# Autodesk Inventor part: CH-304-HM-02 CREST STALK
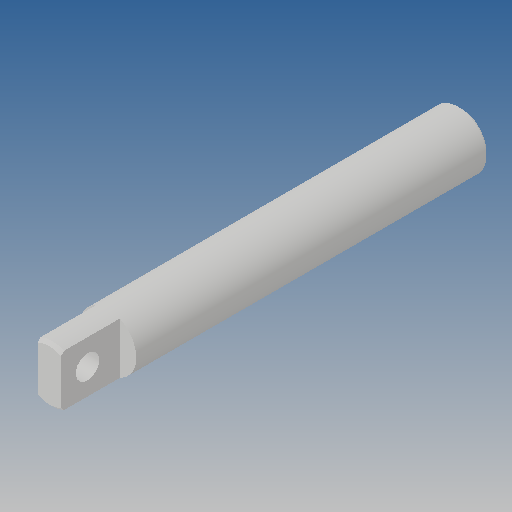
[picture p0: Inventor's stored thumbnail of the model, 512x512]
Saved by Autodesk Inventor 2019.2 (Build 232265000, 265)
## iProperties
Created: 2015-08
Part Number: CH-304-HM-02 CREST STALK
Material: Ogólny
Document SubType Name: Modeling
Designer: CADENGINEERING4
Density: 1 g/cm^3
Appearance: Domyślna
Author: CADENGINEERING4
Revision Number: ÈÎºÎ
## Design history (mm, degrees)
feature "ÇÐ³ý-É¨Ãè1"
node "Bryła1"
